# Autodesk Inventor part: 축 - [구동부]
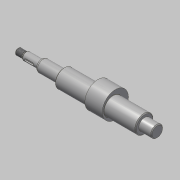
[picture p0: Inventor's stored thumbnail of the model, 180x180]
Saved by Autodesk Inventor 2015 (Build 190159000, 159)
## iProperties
Created: 2015-12
Part Number: 축 - [구동부]
Document SubType Name: Modeling
Designer: mdu
Density: 7.86 g/cm^3
Material: 강철, 연강
Appearance: 강철
Mass: 484.678 g
Surface Area: 125.968 cm^2
Volume: 61.6639 cm^3
Author: mdu
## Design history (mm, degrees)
sketch "스케치1"
  geometry: L1 (62, 100.9)-(62, 67.1) reference; L2 (51, 101.2)-(51, 84) reference; L3 (-51, 84)-(-51, 101.2) reference; L4 (-62, 67.1)-(-62, 100.9) reference; L5 (-51.6, 91.5)-(-61.4, 91.5) reference; L6 (51.6, 91.5)-(61.4, 91.5) reference; L7 (67, 84)-(-109, 84); L8 (-77, 64.201)-(-77, 103.799) reference; L9 (67, 84)-(67, 91.5); L10 (67, 91.5)-(51, 91.5); L11 (51, 91.5)-(51, 95.5); L12 (51, 95.5)-(-51, 95.5); L13 (-51, 95.5)-(-51, 91.5); L14 (-51, 91.5)-(-79, 91.5); L15 (-79, 91.5)-(-79, 89); L16 (-79, 89)-(-99, 89); L17 (-99, 89)-(-99, 87); L18 (-100.5, 88)-(-109, 88); L19 (-109, 88)-(-109, 84); L20 (-99, 87)-(-100.5, 87); L21 (-100.5, 87)-(-100.5, 88); 2 further points
  constraints: 32 end point, 7 parallel, 6 point on line, 5 perpendicular, 2 collinear, 2 horizontal, 1 midpoint, 4 other
  dimensions: "d0" = 5 distance from line of L7.start L1; "d2" = 2 distance between parallel lines of L15 L8; "d3" = 23 diameter of L12 L7; "d4" = 10 diameter of L16 L7; "d5" = 1.5 distance of L17.end L20.end; "d6" = 6 diameter of L20 L7; "d7" = 20 distance of L15.end L16.end; "d8" = 10 distance between parallel lines of L17 L19; "d9" = 8 diameter of L18 L7
revolve "회전1" sketch "스케치1" stored, may be unused: angle "d10" = 90 deg
sketch "스케치2"
  geometry: C1 r 11.5 at (84, 0) reference; C2 r 11.5 at (84, 0) reference; C3 r 16.5 at (87, 0); 1 further point
  constraints: 1 centre point, 1 horizontal alignment
  dimensions: "d11" = 33 diameter of C3; "d12" = 3 distance of C3.centre C1.centre
extrude "돌출1" join sketch "스케치2" stored distance "d13" = 22; taper "d14" = 0 deg
chamfer "모따기1" distance "d15" = 1; stored, may be unused: second distance "d16" = 2, angle "d17" = 45 deg
feature "스레드1" dims "d18" = 10, "d19" = 0
node "작업 평면1"
sketch "스케치3"
  geometry: L1 (-5.5, -1.5)-(3.5, -1.5); L2 (3.5, 1.5)-(-5.5, 1.5); L3 (-10, -4)-(-10, 4) reference; A1 r 1.5 centre (3.5, 0) between (3.5, -1.5) and (3.5, 1.5); A2 r 1.5 centre (-5.5, 0) between (-5.5, 1.5) and (-5.5, -1.5); 2 further points
  constraints: 4 end point, 4 point on circle, 4 tangent, 2 centre point, 1 horizontal, 1 horizontal alignment, 1 midpoint, 1 parallel
  dimensions: "d20" = 3 distance between parallel lines of L1 L2; "d21" = 12 dimension on A1 A2; "d22" = 3 distance edge to line of A2 L3
extrude "돌출2" cut sketch "스케치3" distance "d23" = 1.8; taper "d24" = 0 deg
fillet "모깎기1" dims "d25" = 0.3
fillet "모깎기2" dims "d26" = 3
node "솔리드1"
node "참조1"
node "참조2"
node "참조3"
node "참조4"
node "참조5"
node "투영된 루프1"
